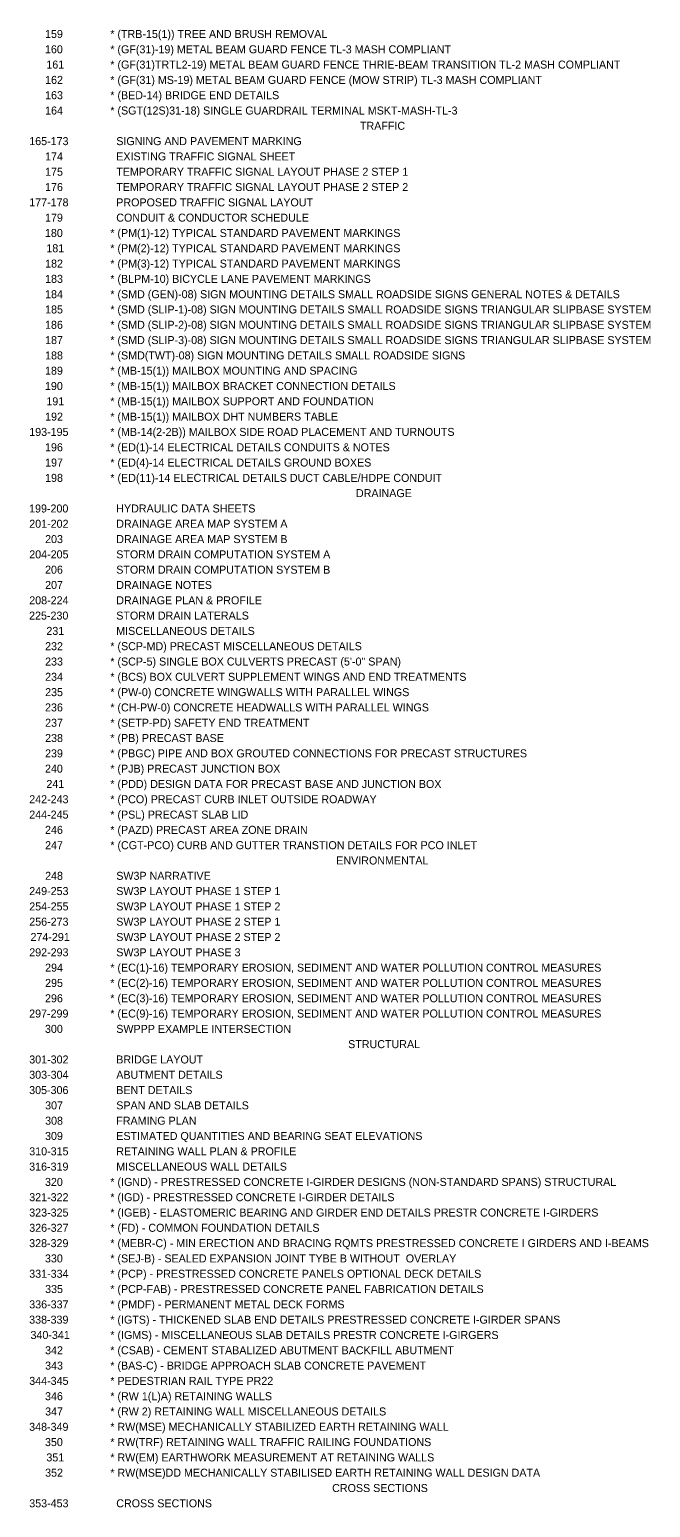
# Model space of a CAD drawing. Extents: x 2147351 to 2147573, y 2147143 to 2147587.
# Drawn here: x 2147477.1 to 2147570.2, y 2147143 to 2147364.6 of the extents above; entities that cross this region are included whole.
import ezdxf

# ---------------------------------------------------------------- set-up
doc = ezdxf.new("R2010")
doc.units = 0
doc.layers.add('Default', color=7, linetype='Continuous')

msp = doc.modelspace()

# ---------------------------------------------------------------- texts
at = {"layer": 'Default'}
for s, p in [('159', (2147479.39, 2147363.34)), ('* (TRB-15(1)) TREE AND BRUSH REMOVAL', (2147489.18, 2147363.34)), ('160', (2147479.38, 2147361.04)), ('* (GF(31)-19) METAL BEAM GUARD FENCE TL-3 MASH COMPLIANT', (2147489.18, 2147361.04)), ('161', (2147479.59, 2147358.75)), ('* (GF(31)TRTL2-19) METAL BEAM GUARD FENCE THRIE-BEAM TRANSITION TL-2 MASH COMPLIANT', (2147489.18, 2147358.75)), ('162', (2147479.4, 2147356.45)), ('* (GF(31) MS-19) METAL BEAM GUARD FENCE (MOW STRIP) TL-3 MASH COMPLIANT', (2147489.18, 2147356.45)), ('163', (2147479.4, 2147354.16)), ('* (BED-14) BRIDGE END DETAILS', (2147489.18, 2147354.16)), ('164', (2147479.4, 2147351.86)), ('* (SGT(12S)31-18) SINGLE GUARDRAIL TERMINAL MSKT-MASH-TL-3', (2147489.18, 2147351.86)), ('TRAFFIC', (2147526.62, 2147349.57)), ('165-173', (2147477.02, 2147347.27)), ('  SIGNING AND PAVEMENT MARKING', (2147489.18, 2147347.27)), ('174', (2147479.4, 2147344.98)), ('  EXISTING TRAFFIC SIGNAL SHEET', (2147489.18, 2147344.98)), ('175', (2147479.4, 2147342.68)), ('  TEMPORARY TRAFFIC SIGNAL LAYOUT PHASE 2 STEP 1', (2147489.18, 2147342.68)), ('176', (2147479.39, 2147340.39)), ('  TEMPORARY TRAFFIC SIGNAL LAYOUT PHASE 2 STEP 2', (2147489.18, 2147340.39)), ('177-178', (2147477.02, 2147338.09)), ('  PROPOSED TRAFFIC SIGNAL LAYOUT', (2147489.18, 2147338.09)), ('179', (2147479.39, 2147335.8)), ('  CONDUIT & CONDUCTOR SCHEDULE', (2147489.18, 2147335.8)), ('180', (2147479.38, 2147333.5)), ('* (PM(1)-12) TYPICAL STANDARD PAVEMENT MARKINGS ', (2147489.18, 2147333.5)), ('181', (2147479.59, 2147331.21)), ('* (PM(2)-12) TYPICAL STANDARD PAVEMENT MARKINGS ', (2147489.18, 2147331.21)), ('182', (2147479.4, 2147328.91)), ('* (PM(3)-12) TYPICAL STANDARD PAVEMENT MARKINGS ', (2147489.18, 2147328.91)), ('183', (2147479.4, 2147326.62)), ('* (BLPM-10) BICYCLE LANE PAVEMENT MARKINGS', (2147489.18, 2147326.62)), ('184', (2147479.4, 2147324.32)), ('* (SMD (GEN)-08) SIGN MOUNTING DETAILS SMALL ROADSIDE SIGNS GENERAL NOTES & DETAILS', (2147489.18, 2147324.32)), ('185', (2147479.4, 2147322.03)), ('* (SMD (SLIP-1)-08) SIGN MOUNTING DETAILS SMALL ROADSIDE SIGNS TRIANGULAR SLIPBASE SYSTEM', (2147489.18, 2147322.03)), ('186', (2147479.39, 2147319.73)), ('* (SMD (SLIP-2)-08) SIGN MOUNTING DETAILS SMALL ROADSIDE SIGNS TRIANGULAR SLIPBASE SYSTEM', (2147489.18, 2147319.73)), ('187', (2147479.4, 2147317.44)), ('* (SMD (SLIP-3)-08) SIGN MOUNTING DETAILS SMALL ROADSIDE SIGNS TRIANGULAR SLIPBASE SYSTEM', (2147489.18, 2147317.44)), ('188', (2147479.4, 2147315.14)), ('* (SMD(TWT)-08) SIGN MOUNTING DETAILS SMALL ROADSIDE SIGNS ', (2147489.18, 2147315.14)), ('189', (2147479.39, 2147312.85)), ('* (MB-15(1)) MAILBOX MOUNTING AND SPACING', (2147489.18, 2147312.85)), ('190', (2147479.38, 2147310.55)), ('* (MB-15(1)) MAILBOX BRACKET CONNECTION DETAILS', (2147489.18, 2147310.55)), ('191', (2147479.59, 2147308.26)), ('* (MB-15(1)) MAILBOX SUPPORT AND FOUNDATION', (2147489.18, 2147308.26)), ('192', (2147479.4, 2147305.96)), ('* (MB-15(1)) MAILBOX DHT NUMBERS TABLE', (2147489.18, 2147305.96)), ('193-195', (2147477.02, 2147303.67)), ('* (MB-14(2-2B)) MAILBOX SIDE ROAD PLACEMENT AND TURNOUTS', (2147489.18, 2147303.67)), ('196', (2147479.39, 2147301.37)), ('* (ED(1)-14 ELECTRICAL DETAILS CONDUITS & NOTES', (2147489.18, 2147301.37)), ('197', (2147479.4, 2147299.08)), ('* (ED(4)-14 ELECTRICAL DETAILS GROUND BOXES', (2147489.18, 2147299.08)), ('198', (2147479.4, 2147296.78)), ('* (ED(11)-14 ELECTRICAL DETAILS DUCT CABLE/HDPE CONDUIT', (2147489.18, 2147296.78)), ('DRAINAGE', (2147526.02, 2147294.49)), ('199-200', (2147477, 2147292.19)), ('  HYDRAULIC DATA SHEETS', (2147489.18, 2147292.19)), ('201-202', (2147477.02, 2147289.9)), ('  DRAINAGE AREA MAP SYSTEM A', (2147489.18, 2147289.9)), ('203', (2147479.4, 2147287.6)), ('  DRAINAGE AREA MAP SYSTEM B', (2147489.18, 2147287.6)), ('204-205', (2147477.02, 2147285.31)), ('  STORM DRAIN COMPUTATION SYSTEM A', (2147489.18, 2147285.31)), ('206', (2147479.39, 2147283.01)), ('  STORM DRAIN COMPUTATION SYSTEM B', (2147489.18, 2147283.01)), ('207', (2147479.4, 2147280.72)), ('  DRAINAGE NOTES', (2147489.18, 2147280.72)), ('208-224', (2147477.02, 2147278.42)), ('  DRAINAGE PLAN & PROFILE', (2147489.18, 2147278.42)), ('225-230', (2147477, 2147276.13)), ('  STORM DRAIN LATERALS', (2147489.18, 2147276.13)), ('231', (2147479.59, 2147273.83)), ('  MISCELLANEOUS DETAILS   ', (2147489.18, 2147273.83)), ('232', (2147479.4, 2147271.54)), ('* (SCP-MD) PRECAST MISCELLANEOUS DETAILS', (2147489.18, 2147271.54)), ('233', (2147479.4, 2147269.24)), ('* (SCP-5) SINGLE BOX CULVERTS PRECAST (5\'-0" SPAN)', (2147489.18, 2147269.24)), ('234', (2147479.4, 2147266.95)), ('* (BCS) BOX CULVERT SUPPLEMENT WINGS AND END TREATMENTS', (2147489.18, 2147266.95)), ('235', (2147479.4, 2147264.65)), ('* (PW-0) CONCRETE WINGWALLS WITH PARALLEL WINGS', (2147489.18, 2147264.65)), ('236', (2147479.39, 2147262.36)), ('* (CH-PW-0) CONCRETE HEADWALLS WITH PARALLEL WINGS', (2147489.18, 2147262.36)), ('237', (2147479.4, 2147260.06)), ('* (SETP-PD) SAFETY END TREATMENT', (2147489.18, 2147260.06)), ('238', (2147479.4, 2147257.77)), ('* (PB) PRECAST BASE', (2147489.18, 2147257.77)), ('239', (2147479.39, 2147255.47)), ('* (PBGC) PIPE AND BOX GROUTED CONNECTIONS FOR PRECAST STRUCTURES', (2147489.18, 2147255.47)), ('240', (2147479.38, 2147253.18)), ('* (PJB) PRECAST JUNCTION BOX', (2147489.18, 2147253.18)), ('241', (2147479.59, 2147250.88)), ('* (PDD) DESIGN DATA FOR PRECAST BASE AND JUNCTION BOX', (2147489.18, 2147250.88)), ('242-243', (2147477.02, 2147248.59)), ('* (PCO) PRECAST CURB INLET OUTSIDE ROADWAY', (2147489.18, 2147248.59)), ('244-245', (2147477.02, 2147246.29)), ('* (PSL) PRECAST SLAB LID', (2147489.18, 2147246.29)), ('246', (2147479.39, 2147244)), ('* (PAZD) PRECAST AREA ZONE DRAIN', (2147489.18, 2147244)), ('247', (2147479.4, 2147241.7)), ('* (CGT-PCO) CURB AND GUTTER TRANSTION DETAILS FOR PCO INLET', (2147489.18, 2147241.7)), ('ENVIRONMENTAL', (2147523.07, 2147239.41)), ('248', (2147479.4, 2147237.11)), ('  SW3P NARRATIVE', (2147489.18, 2147237.11)), ('249-253', (2147477.02, 2147234.82)), ('  SW3P LAYOUT PHASE 1 STEP 1', (2147489.18, 2147234.82)), ('254-255', (2147477.02, 2147232.52)), ('  SW3P LAYOUT PHASE 1 STEP 2', (2147489.18, 2147232.52)), ('256-273', (2147477.02, 2147230.23)), ('  SW3P LAYOUT PHASE 2 STEP 1', (2147489.18, 2147230.23)), ('274-291', (2147477.21, 2147227.93)), ('  SW3P LAYOUT PHASE 2 STEP 2', (2147489.18, 2147227.93)), ('292-293', (2147477.02, 2147225.64)), ('  SW3P LAYOUT PHASE 3', (2147489.18, 2147225.64)), ('294', (2147479.4, 2147223.34)), ('* (EC(1)-16) TEMPORARY EROSION, SEDIMENT AND WATER POLLUTION CONTROL MEASURES', (2147489.18, 2147223.34)), ('295', (2147479.4, 2147221.05)), ('* (EC(2)-16) TEMPORARY EROSION, SEDIMENT AND WATER POLLUTION CONTROL MEASURES', (2147489.18, 2147221.05)), ('296', (2147479.39, 2147218.75)), ('* (EC(3)-16) TEMPORARY EROSION, SEDIMENT AND WATER POLLUTION CONTROL MEASURES', (2147489.18, 2147218.75)), ('297-299', (2147477.01, 2147216.46)), ('* (EC(9)-16) TEMPORARY EROSION, SEDIMENT AND WATER POLLUTION CONTROL MEASURES', (2147489.18, 2147216.46)), ('300', (2147479.38, 2147214.16)), ('  SWPPP EXAMPLE INTERSECTION', (2147489.18, 2147214.16)), ('STRUCTURAL', (2147524.85, 2147211.87)), ('301-302', (2147477.02, 2147209.57)), ('  BRIDGE LAYOUT', (2147489.18, 2147209.57)), ('303-304', (2147477.02, 2147207.28)), ('  ABUTMENT DETAILS', (2147489.18, 2147207.28)), ('305-306', (2147477.01, 2147204.98)), ('  BENT DETAILS', (2147489.18, 2147204.98)), ('307', (2147479.4, 2147202.69)), ('  SPAN AND SLAB DETAILS', (2147489.18, 2147202.69)), ('308', (2147479.4, 2147200.39)), ('  FRAMING PLAN', (2147489.18, 2147200.39)), ('309', (2147479.39, 2147198.1)), ('  ESTIMATED QUANTITIES AND BEARING SEAT ELEVATIONS', (2147489.18, 2147198.1)), ('310-315', (2147477.02, 2147195.8)), ('  RETAINING WALL PLAN & PROFILE', (2147489.18, 2147195.8)), ('316-319', (2147477.01, 2147193.51)), ('  MISCELLANEOUS WALL DETAILS', (2147489.18, 2147193.51)), ('320', (2147479.38, 2147191.21)), ('* (IGND) - PRESTRESSED CONCRETE I-GIRDER DESIGNS (NON-STANDARD SPANS) STRUCTURAL', (2147489.18, 2147191.21)), ('321-322', (2147477.02, 2147188.92)), ('* (IGD) - PRESTRESSED CONCRETE I-GIRDER DETAILS', (2147489.18, 2147188.92)), ('323-325', (2147477.02, 2147186.62)), ('* (IGEB) - ELASTOMERIC BEARING AND GIRDER END DETAILS PRESTR CONCRETE I-GIRDERS', (2147489.18, 2147186.62)), ('326-327', (2147477.02, 2147184.33)), ('* (FD) - COMMON FOUNDATION DETAILS', (2147489.18, 2147184.33)), ('328-329', (2147477.01, 2147182.03)), ('* (MEBR-C) - MIN ERECTION AND BRACING RQMTS PRESTRESSED CONCRETE I GIRDERS AND I-BEAMS', (2147489.18, 2147182.03)), ('330', (2147479.38, 2147179.74)), ('* (SEJ-B) - SEALED EXPANSION JOINT TYBE B WITHOUT  OVERLAY', (2147489.18, 2147179.74)), ('331-334', (2147477.02, 2147177.44)), ('* (PCP) - PRESTRESSED CONCRETE PANELS OPTIONAL DECK DETAILS', (2147489.18, 2147177.44)), ('335', (2147479.4, 2147175.15)), ('* (PCP-FAB) - PRESTRESSED CONCRETE PANEL FABRICATION DETAILS', (2147489.18, 2147175.15)), ('336-337', (2147477.02, 2147172.85)), ('* (PMDF) - PERMANENT METAL DECK FORMS', (2147489.18, 2147172.85)), ('338-339', (2147477.01, 2147170.56)), ('* (IGTS) - THICKENED SLAB END DETAILS PRESTRESSED CONCRETE I-GIRDER SPANS', (2147489.18, 2147170.56)), ('340-341', (2147477.21, 2147168.26)), ('* (IGMS) - MISCELLANEOUS SLAB DETAILS PRESTR CONCRETE I-GIRGERS', (2147489.18, 2147168.26)), ('342', (2147479.4, 2147165.97)), ('* (CSAB) - CEMENT STABALIZED ABUTMENT BACKFILL ABUTMENT', (2147489.18, 2147165.97)), ('343', (2147479.4, 2147163.67)), ('* (BAS-C) - BRIDGE APPROACH SLAB CONCRETE PAVEMENT', (2147489.18, 2147163.67)), ('344-345', (2147477.02, 2147161.38)), ('* PEDESTRIAN RAIL TYPE PR22', (2147489.18, 2147161.38)), ('346', (2147479.39, 2147159.08)), ('* (RW 1(L)A) RETAINING WALLS', (2147489.18, 2147159.08)), ('347', (2147479.4, 2147156.79)), ('* (RW 2) RETAINING WALL MISCELLANEOUS DETAILS', (2147489.18, 2147156.79)), ('348-349', (2147477.01, 2147154.49)), ('* RW(MSE) MECHANICALLY STABILIZED EARTH RETAINING WALL', (2147489.18, 2147154.49)), ('350', (2147479.38, 2147152.2)), ('* RW(TRF) RETAINING WALL TRAFFIC RAILING FOUNDATIONS ', (2147489.18, 2147152.2)), ('351', (2147479.59, 2147149.9)), ('* RW(EM) EARTHWORK MEASUREMENT AT RETAINING WALLS', (2147489.18, 2147149.9)), ('352', (2147479.4, 2147147.61)), ('* RW(MSE)DD MECHANICALLY STABILISED EARTH RETAINING WALL DESIGN DATA', (2147489.18, 2147147.61)), ('CROSS SECTIONS', (2147522.45, 2147145.31)), ('353-453', (2147477.02, 2147143.02)), ('  CROSS SECTIONS', (2147489.18, 2147143.02))]:
    msp.add_text(s, height=1.2, dxfattribs=at).set_placement(p)

doc.saveas('drawing.dxf')
